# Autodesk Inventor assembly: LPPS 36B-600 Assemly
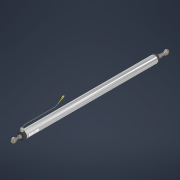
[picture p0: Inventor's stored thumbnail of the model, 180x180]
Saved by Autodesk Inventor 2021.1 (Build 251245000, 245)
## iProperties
Created: 2020-09
Part Number: LPPS 36B-600 Assemly
Document SubType Name: Assembly
Designer: J. Nielson
Author: J. Nielson
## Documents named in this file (3)
- C:\Users\Justin\Documents\CAD\The Sensor Connection\LPPS\LPPS-36B Series\3D\LPPS-36B-600\LPPS 36B-600 Assemly.iam
- C:\Users\Justin\Documents\CAD\The Sensor Connection\LPPS\LPPS-36B Series\3D\LPPS-36B-600\LPPS 36B-600 Shaft_Shrinkwrap.ipt
- C:\Users\Justin\Documents\CAD\The Sensor Connection\LPPS\LPPS-36B Series\3D\LPPS-36B-600\LPPS 36B-600_Shrinkwrap.ipt
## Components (2 placed, 2 different names)
1. LPPS 36B-600 Shaft_Shrinkwrap:1 — Mate:1, Mate:2, Cylindrical:1
2. LPPS 36B-600_Shrinkwrap:1 — Mate:1, Cylindrical:1
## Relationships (3: Mate 2, CylindricalJoint 1)
- Mate:1: LPPS 36B-600 Shaft_Shrinkwrap:1 ↔ LPPS 36B-600_Shrinkwrap:1
- Mate:2: LPPS 36B-600 Shaft_Shrinkwrap:1
- Cylindrical:1: LPPS 36B-600 Shaft_Shrinkwrap:1 ↔ LPPS 36B-600_Shrinkwrap:1
